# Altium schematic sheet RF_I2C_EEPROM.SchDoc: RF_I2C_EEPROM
size A4; DocumentNumber: MB1144; Revision: B-02; SheetNumber: 22; SheetTotal: 25; Project: STM32L476G-EVAL
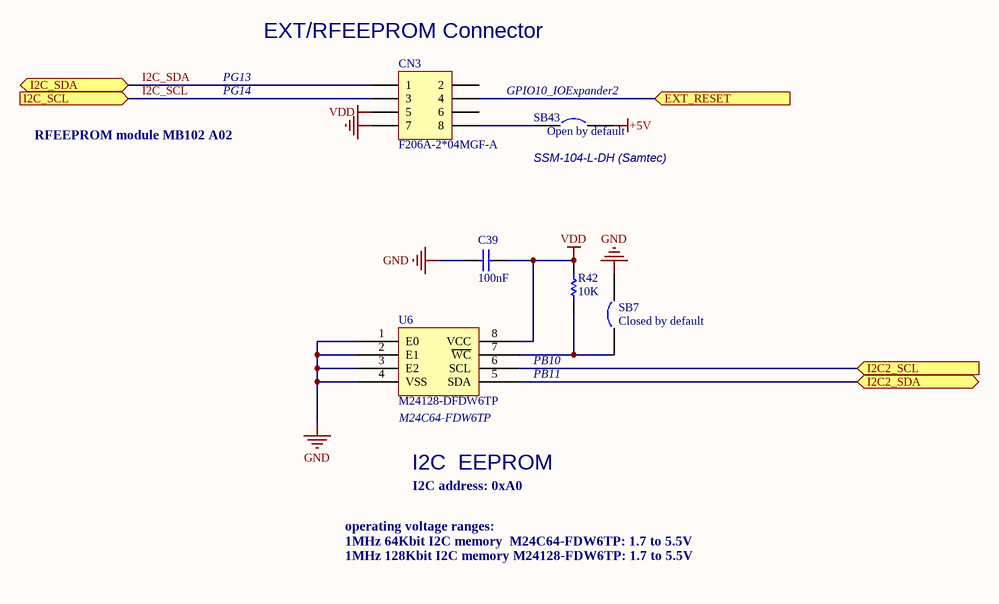
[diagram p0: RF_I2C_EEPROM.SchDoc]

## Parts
C39  100nF  [0402C]
CN3  F206A-2*04MGF-A  [SSM-104-L-DH]
R42  10K  [0402R]
SB7  Closed by default  [SB_0603]
SB43  Open by default  [SB_0603]
U6  M24128-DFDW6TP  [TSSOP8_0R65_3X6R4]

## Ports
EXT_RESET (in), I2C2_SCL (in), I2C2_SDA (bidir), I2C_SCL (in), I2C_SDA (bidir)

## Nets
+5V: SB43.2
GND: C39.1 CN3.7 SB7.2 U6.1(E0) U6.2(E1) U6.3(E2) U6.4(VSS)
VDD: C39.2 CN3.5 R42.1 U6.8(VCC)
EXT_RESET: CN3.4 ; port EXT_RESET
I2C2_SCL: U6.6(SCL) ; port I2C2_SCL
I2C2_SDA: U6.5(SDA) ; port I2C2_SDA
I2C_SCL: CN3.3 ; port I2C_SCL
I2C_SDA: CN3.1 ; port I2C_SDA
NetCN3_8: CN3.8 SB43.1
NetR42_2: R42.2 SB7.1 U6.7(~{WC})

Not connected (* = marked no-connect by the designer): CN3 2 6

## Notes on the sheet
- PG13
- (near CN3) EXT/RFEEPROM Connector
- RFEEPROM module MB102 A02
  I2C address: 0xA6
- PG14
- (near SB43) GPIO10_IOExpander2
- SSM-104-L-DH (Samtec)
- PB11
- PB10
- (near U6) M24C64-FDW6TP
- I2C  EEPROM
- I2C address: 0xA0
- operating voltage ranges:
  1MHz 64Kbit I2C memory  M24C64-FDW6TP: 1.7 to 5.5V
  1MHz 128Kbit I2C memory M24128-FDW6TP: 1.7 to 5.5V

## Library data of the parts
C39 = CAP: Capacitor; Value: 100pF; Ordered by: Subcon; ECCN_US/EU: NA
CN3 = SSM-104-L-DH: Header, 5-Pin, Dual row; Ordered by: Subcon; Comments: EXT/RF E2P connector; ECCN_US/EU: NA; Assembly: with MB1020 A02
R42 = Res1: Resistor; Value: 1K; Ordered by: Subcon; ECCN_US/EU: NA
SB7 = Circuit Breaker: Ordered by: Subcon; Comments: Solder bridge; ECCN_US/EU: NA
SB43 = Circuit Breaker: Ordered by: Subcon; Comments: Solder bridge; Fitted: NO; ECCN_US/EU: NA
U6 = M24C64-WMN6: Ordered by: ST; ECCN_US/EU: EAR99/NEC; Ref St: 9175653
